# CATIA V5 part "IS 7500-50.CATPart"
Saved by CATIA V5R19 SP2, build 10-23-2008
Part number: IS 7500-50
Bounding box of the stored display mesh (mm): x -74.81 to 74.81, y -74.81 to 74.81, z 0 to 255
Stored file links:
  C:\Users\Bora\Desktop\3D Katı model\IS serisi\IS 7500\IS 7500-50.CATPart
  C:\Program Files\Dassault Systemes\B19\intel_a\reffiles\standard\MetricThickPitch.txt
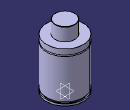
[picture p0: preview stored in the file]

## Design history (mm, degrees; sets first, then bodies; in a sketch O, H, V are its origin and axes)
Body1 (main body)
  Sketch1 on yz-plane, origin (0, 0, 0), H (0, 1, 0), V (0, 0, 1)
    point P1 (75, 180)
    point P2 (75, 175)
    point P5 (40, 254)
    point P7 (40, 254)
    point P12 (75, 175)
    point P13 (75, 180)
    arc A1 centre (75, 177.5) radius 2.5 from (75, 180) to (75, 175) ccw
    line L1 (75, 0) -> (75, 8)
    line L2 (40, 254) -> (40, 202)
    arc A2 centre (39, 254) radius 1 from (40, 254) to (39, 255) ccw
    line L3 (71, 15) -> (71, 8)
    line L4 (75, 15) -> (75, 175)
    line L5 (75, 180) -> (75, 202)
    line L6 (39, 255) -> (0, 255)
    point P15 (0, 255)
    line L7 (40, 202) -> (75, 202)
    line L8 (0, 0) -> (75, 0)
    line L9 (71, 8) -> (75, 8)
    line L10 (71, 15) -> (75, 15)
    coincidence: P15 V, P1 P13, P2 P12, P5 P7
    tangency: L6 A2
    horizontal: L7 H, L8 H, L9 H, L10 H
  Shaft1: profile Sketch1, axis Sketch1.V, angle 360
  Sketch2 on face of Shaft1 from Sketch1.L8, origin (0, 0, 0), H (1, 0, 0), V (0, -1, 0)
    point P1 (50, 0)
    distance P1 V = 50
  Hole1: placed by Sketch2, at (50, 0, 0) direction (0, 0, 1), diameter 8.376, depth 16, threaded "M10", thread diameter 10, thread depth 16, pitch 1.5
  CircPattern1: of Hole1, instances 4, angular step 90, axis from xy-plane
